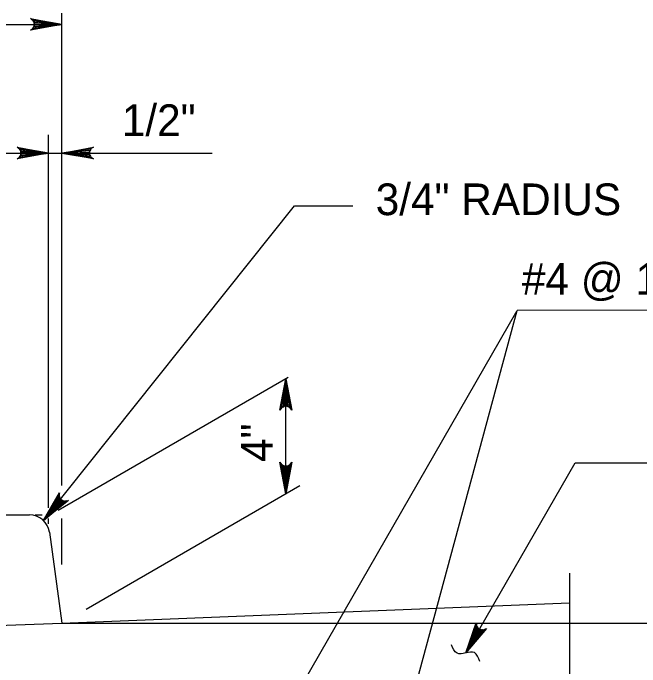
# Model space of a CAD drawing. Extents: x 2084213 to 2099800, y 976677 to 981262.
# Drawn here: x 2095231.3 to 2095426.2, y 977060 to 977263.3 of the extents above; entities that cross this region are included whole.
import ezdxf

# ---------------------------------------------------------------- set-up
doc = ezdxf.new("R2010")
doc.units = 0
doc.layers.add('1', color=7, linetype='Continuous')

msp = doc.modelspace()

# ---------------------------------------------------------------- linework, layer by layer
at = {"layer": '1'}
for p, q in [((2095246.45, 977116.41), (2095246.45, 977263.26)), ((2095179.78, 977259.75), (2095246.45, 977259.75)), ((2095242.29, 977109.44), (2095242.29, 977225.42)), ((2095179.78, 977219.75), (2095293.16, 977219.75)), ((2095240.71, 977105.53), (2095318.83, 977203.35)), ((2095318.83, 977203.35), (2095336.96, 977203.35)), ((2095314.6, 977043.1), (2095388.08, 977170.82)), ((2095354.78, 977047.83), (2095388.08, 977170.82)), ((2095459.73, 977170.94), (2095388.08, 977170.82)), ((2095245.25, 977108.72), (2095316.83, 977150.05)), ((2095316.09, 977113.88), (2095316.09, 977149.62)), ((2095372.04, 977064.37), (2095406.06, 977123.5)), ((2095406.06, 977123.5), (2095445.03, 977123.5)), ((2095253.99, 977078.02), (2095320.4, 977116.37)), ((2095181.86, 977107.28), (2095236.37, 977107.28)), ((2095238.14, 977107.28), (2095240.29, 977107.28)), ((2095242.29, 977104.51), (2095242.29, 977106.15)), ((2095246.45, 977091.9), (2095246.45, 977106.15)), ((2095242.56, 977101.89), (2095246.45, 977073.67)), ((2095404.32, 977089.22), (2095404.32, 977034.38)), ((2095246.45, 977073.67), (2095404.32, 977079.99)), ((2095179.78, 977071), (2095246.45, 977073.67)), ((2095246.45, 977073.67), (2095498.16, 977073.67))]:
    msp.add_line(p, q, dxfattribs=at)
for points in [[(2095246.45, 977259.75), (2095236.66, 977257.91), (2095237.04, 977258.17), (2095237.42, 977258.43), (2095237.61, 977258.76), (2095237.81, 977259.09), (2095237.86, 977259.42), (2095237.92, 977259.75), (2095237.86, 977260.07), (2095237.81, 977260.4), (2095237.61, 977260.73), (2095237.42, 977261.06), (2095237.04, 977261.32), (2095236.66, 977261.58), (2095246.45, 977259.75), (2095237.04, 977261.32), (2095237.42, 977261.06), (2095246.45, 977259.75), (2095237.61, 977260.73), (2095237.81, 977260.4), (2095246.45, 977259.75), (2095237.86, 977260.07), (2095237.92, 977259.75), (2095246.45, 977259.75), (2095237.86, 977259.42), (2095237.81, 977259.09), (2095246.45, 977259.75), (2095237.61, 977258.76), (2095237.42, 977258.43), (2095246.45, 977259.75), (2095237.04, 977258.17)], [(2095242.29, 977219.75), (2095232.5, 977217.91), (2095232.88, 977218.17), (2095233.26, 977218.43), (2095233.45, 977218.76), (2095233.65, 977219.09), (2095233.7, 977219.42), (2095233.76, 977219.75), (2095233.7, 977220.07), (2095233.65, 977220.4), (2095233.45, 977220.73), (2095233.26, 977221.06), (2095232.88, 977221.32), (2095232.5, 977221.58), (2095242.29, 977219.75), (2095232.88, 977221.32), (2095233.26, 977221.06), (2095242.29, 977219.75), (2095233.45, 977220.73), (2095233.65, 977220.4), (2095242.29, 977219.75), (2095233.7, 977220.07), (2095233.76, 977219.75), (2095242.29, 977219.75), (2095233.7, 977219.42), (2095233.65, 977219.09), (2095242.29, 977219.75), (2095233.45, 977218.76), (2095233.26, 977218.43), (2095242.29, 977219.75), (2095232.88, 977218.17)], [(2095246.45, 977219.75), (2095256.23, 977221.58), (2095255.86, 977221.32), (2095255.48, 977221.06), (2095255.29, 977220.73), (2095255.09, 977220.4), (2095255.03, 977220.07), (2095254.98, 977219.75), (2095255.03, 977219.42), (2095255.09, 977219.09), (2095255.29, 977218.76), (2095255.48, 977218.43), (2095255.86, 977218.17), (2095256.23, 977217.91), (2095246.45, 977219.75), (2095255.86, 977218.17), (2095255.48, 977218.43), (2095246.45, 977219.75), (2095255.29, 977218.76), (2095255.09, 977219.09), (2095246.45, 977219.75), (2095255.03, 977219.42), (2095254.98, 977219.75), (2095246.45, 977219.75), (2095255.03, 977220.07), (2095255.09, 977220.4), (2095246.45, 977219.75), (2095255.29, 977220.73), (2095255.48, 977221.06), (2095246.45, 977219.75), (2095255.86, 977221.32)], [(2095316.09, 977149.62), (2095317.93, 977139.83), (2095317.67, 977140.21), (2095317.4, 977140.59), (2095317.08, 977140.78), (2095316.75, 977140.98), (2095316.42, 977141.03), (2095316.09, 977141.09), (2095315.76, 977141.03), (2095315.44, 977140.98), (2095315.11, 977140.78), (2095314.78, 977140.59), (2095314.52, 977140.21), (2095314.26, 977139.83), (2095316.09, 977149.62), (2095314.52, 977140.21), (2095314.78, 977140.59), (2095316.09, 977149.62), (2095315.11, 977140.78), (2095315.44, 977140.98), (2095316.09, 977149.62), (2095315.76, 977141.03), (2095316.09, 977141.09), (2095316.09, 977149.62), (2095316.42, 977141.03), (2095316.75, 977140.98), (2095316.09, 977149.62), (2095317.08, 977140.78), (2095317.4, 977140.59), (2095316.09, 977149.62), (2095317.67, 977140.21)], [(2095316.09, 977113.88), (2095314.26, 977123.67), (2095314.52, 977123.29), (2095314.78, 977122.91), (2095315.11, 977122.72), (2095315.44, 977122.52), (2095315.76, 977122.47), (2095316.09, 977122.41), (2095316.42, 977122.47), (2095316.75, 977122.52), (2095317.08, 977122.72), (2095317.4, 977122.91), (2095317.67, 977123.29), (2095317.93, 977123.67), (2095316.09, 977113.88), (2095317.67, 977123.29), (2095317.4, 977122.91), (2095316.09, 977113.88), (2095317.08, 977122.72), (2095316.75, 977122.52), (2095316.09, 977113.88), (2095316.42, 977122.47), (2095316.09, 977122.41), (2095316.09, 977113.88), (2095315.76, 977122.47), (2095315.44, 977122.52), (2095316.09, 977113.88), (2095315.11, 977122.72), (2095314.78, 977122.91), (2095316.09, 977113.88), (2095314.52, 977123.29)], [(2095240.71, 977105.53), (2095245.68, 977114.15), (2095245.63, 977113.7), (2095245.59, 977113.24), (2095245.71, 977112.88), (2095245.83, 977112.52), (2095246.05, 977112.26), (2095246.26, 977112.01), (2095246.54, 977111.84), (2095246.83, 977111.67), (2095247.21, 977111.6), (2095247.58, 977111.53), (2095248.03, 977111.65), (2095248.47, 977111.77), (2095240.71, 977105.53), (2095248.03, 977111.65), (2095247.58, 977111.53), (2095240.71, 977105.53), (2095247.21, 977111.6), (2095246.83, 977111.67), (2095240.71, 977105.53), (2095246.54, 977111.84), (2095246.26, 977112.01), (2095240.71, 977105.53), (2095246.05, 977112.26), (2095245.83, 977112.52), (2095240.71, 977105.53), (2095245.71, 977112.88), (2095245.59, 977113.24), (2095240.71, 977105.53), (2095245.63, 977113.7)], [(2095372.04, 977064.37), (2095375.33, 977073.77), (2095375.37, 977073.31), (2095375.41, 977072.86), (2095375.59, 977072.53), (2095375.78, 977072.19), (2095376.04, 977071.98), (2095376.29, 977071.77), (2095376.61, 977071.65), (2095376.92, 977071.54), (2095377.3, 977071.54), (2095377.68, 977071.55), (2095378.1, 977071.74), (2095378.51, 977071.94), (2095372.04, 977064.37), (2095378.1, 977071.74), (2095377.68, 977071.55), (2095372.04, 977064.37), (2095377.3, 977071.54), (2095376.92, 977071.54), (2095372.04, 977064.37), (2095376.61, 977071.65), (2095376.29, 977071.77), (2095372.04, 977064.37), (2095376.04, 977071.98), (2095375.78, 977072.19), (2095372.04, 977064.37), (2095375.59, 977072.53), (2095375.41, 977072.86), (2095372.04, 977064.37), (2095375.37, 977073.31)]]:
    msp.add_lwpolyline(points, dxfattribs=at)
msp.add_arc((2095236.37, 977101.03), 6.25, 7.849, 90, dxfattribs=at)
msp.add_spline([(2095376.42, 977061.73), (2095374.72, 977064.46), (2095369.33, 977064.29), (2095367.59, 977066.86)], degree=3, dxfattribs=at)

# ---------------------------------------------------------------- texts
for s, height, p in [('1/2"', 9.843, (2095265.08, 977225.04)), ('3/4" RADIUS', 9.8425, (2095344.04, 977200.45)), ('#4 @ 12"', 9.843, (2095389.52, 977175.71))]:
    msp.add_text(s, height=height, dxfattribs=at).set_placement(p)
msp.add_text('4"', height=9.843, rotation=90, dxfattribs=at).set_placement((2095311.95, 977123.71))

doc.saveas('drawing.dxf')
